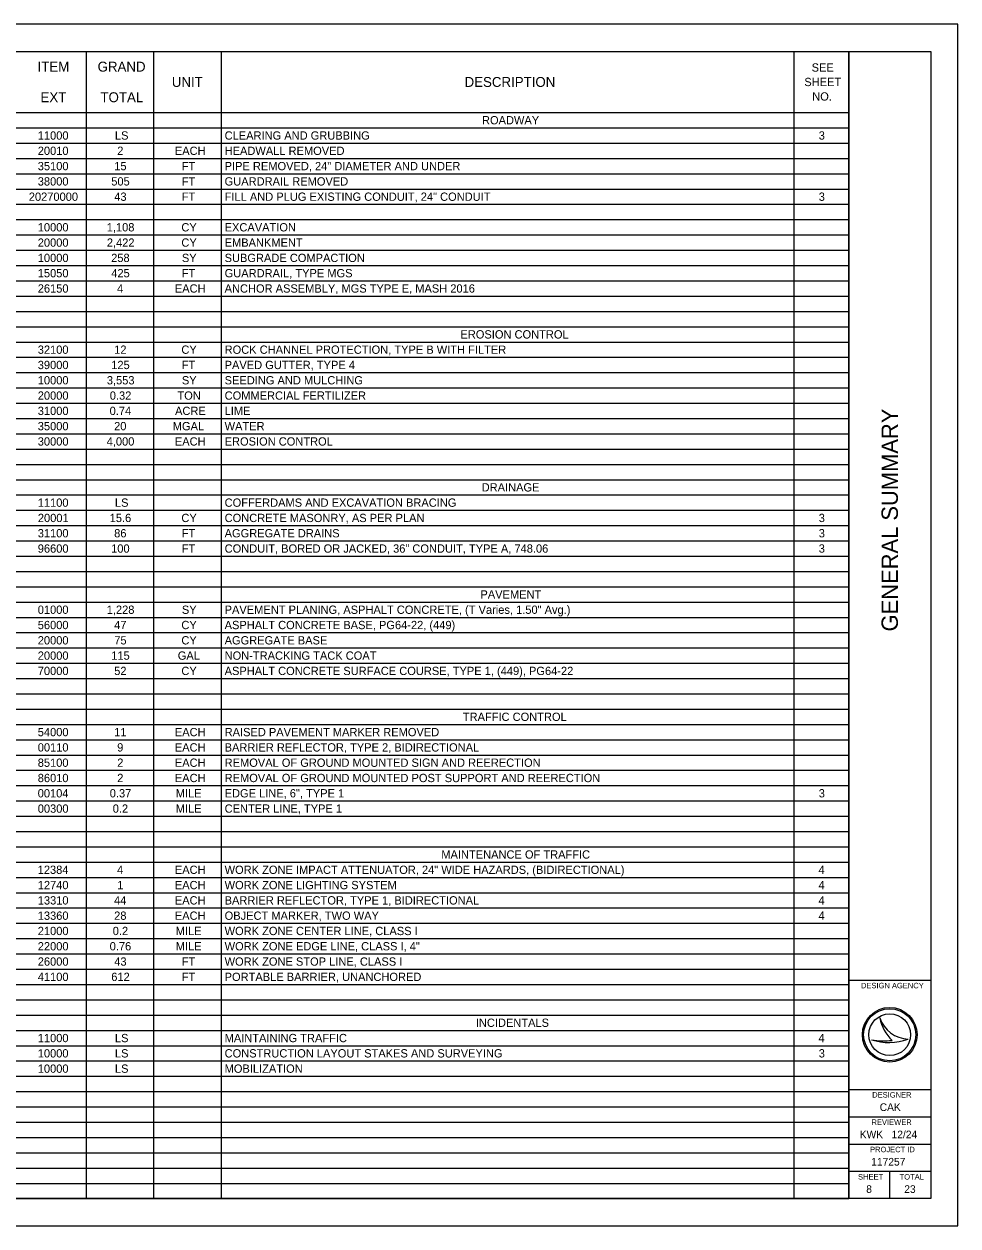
# Model space of a CAD drawing. Extents: x 0 to 34, y 0 to 22.
# Drawn here: x 16.9 to 34, y 0 to 22 of the extents above; entities that cross this region are included whole.
import ezdxf

# ---------------------------------------------------------------- set-up
doc = ezdxf.new("R2010")
doc.units = 0
for name, color, linetype in [('SH_Border', 7, 'Continuous'), ('SH_Cut_Line', 7, 'Continuous'), ('SH_Data', 7, 'Continuous'), ('SH_Text', 7, 'Continuous')]:
    doc.layers.add(name, color=color, linetype=linetype)

msp = doc.modelspace()

# ---------------------------------------------------------------- linework, layer by layer
at = {"layer": 'SH_Border'}
for p, q in [((32, 0.5), (32, 21.5)), ((32, 4.5), (33.5, 4.5)), ((32, 2.5), (33.5, 2.5)), ((32, 2), (33.5, 2)), ((32, 1.5), (33.5, 1.5)), ((32, 1), (33.5, 1))]:
    msp.add_line(p, q, dxfattribs=at)
msp.add_lwpolyline([(1.5, 21.5), (33.5, 21.5), (33.5, 0.5), (1.5, 0.5)], close=True, dxfattribs=at)
at = {"layer": 'SH_Cut_Line'}
msp.add_lwpolyline([(0, 0), (34, 0), (34, 22), (0, 22)], close=True, dxfattribs=at)
at = {"layer": 'SH_Data'}
for p, q in [((32.567, 3.81), (32.567, 3.81)), ((32.417, 3.41), (32.417, 3.41)), ((32.75, 3.5), (32.75, 3.5)), ((33.087, 3.419), (33.087, 3.419)), ((32.75, 0.5), (32.75, 1)), ((32.375, 0.675), (32.375, 0.675))]:
    msp.add_line(p, q, dxfattribs=at)
for radius in [0.5, 0.477, 0.477, 0.382]:
    msp.add_circle((32.75, 3.5), radius, dxfattribs=at)
for centre, radius, start, end in [((33.116, 3.998), 0.58, 198.9257, 198.9319), ((33.347, 3.97), 0.796, 191.6379, 191.6421), ((33.116, 3.998), 0.58, 198.9319, 267.1657), ((33.347, 3.97), 0.796, 191.6421, 226.0947), ((32.739, 4.37), 1.013, 251.4576, 290.0832), ((32.648, 4.654), 1.266, 259.4964, 259.4995), ((32.739, 4.37), 1.013, 251.4527, 251.4576), ((32.648, 4.654), 1.266, 259.4995, 276.6672)]:
    msp.add_arc(centre, radius, start, end, dxfattribs=at)
at = {"layer": 'SH_Text'}
for p, q in [((1.5, 21.5), (32, 21.5)), ((18.035, 21.5), (18.035, 0.5)), ((19.27, 21.5), (19.27, 0.5)), ((20.505, 21.5), (20.505, 0.5)), ((30.995, 21.5), (30.995, 0.5)), ((32, 21.5), (32, 0.5)), ((1.5, 20.38), (32, 20.38)), ((1.5, 20.1), (32, 20.1)), ((1.5, 19.82), (32, 19.82)), ((1.5, 19.54), (32, 19.54)), ((1.5, 19.26), (32, 19.26)), ((1.5, 18.98), (32, 18.98)), ((1.5, 18.7), (32, 18.7)), ((1.5, 18.42), (32, 18.42)), ((1.5, 18.14), (32, 18.14)), ((1.5, 17.86), (32, 17.86)), ((1.5, 17.58), (32, 17.58)), ((1.5, 17.3), (32, 17.3)), ((1.5, 17.02), (32, 17.02)), ((1.5, 16.74), (32, 16.74)), ((1.5, 16.46), (32, 16.46)), ((1.5, 16.18), (32, 16.18)), ((1.5, 15.9), (32, 15.9)), ((1.5, 15.62), (32, 15.62)), ((1.5, 15.34), (32, 15.34)), ((1.5, 15.06), (32, 15.06)), ((1.5, 14.78), (32, 14.78)), ((1.5, 14.5), (32, 14.5)), ((1.5, 14.22), (32, 14.22)), ((1.5, 13.94), (32, 13.94)), ((1.5, 13.66), (32, 13.66)), ((1.5, 13.38), (32, 13.38)), ((1.5, 13.1), (32, 13.1)), ((1.5, 12.82), (32, 12.82)), ((1.5, 12.54), (32, 12.54)), ((1.5, 12.26), (32, 12.26)), ((1.5, 11.98), (32, 11.98)), ((1.5, 11.7), (32, 11.7)), ((1.5, 11.42), (32, 11.42)), ((1.5, 11.14), (32, 11.14)), ((1.5, 10.86), (32, 10.86)), ((1.5, 10.58), (32, 10.58)), ((1.5, 10.3), (32, 10.3)), ((1.5, 10.02), (32, 10.02)), ((1.5, 9.74), (32, 9.74)), ((1.5, 9.46), (32, 9.46)), ((1.5, 9.18), (32, 9.18)), ((1.5, 8.9), (32, 8.9)), ((1.5, 8.62), (32, 8.62)), ((1.5, 8.34), (32, 8.34)), ((1.5, 8.06), (32, 8.06)), ((1.5, 7.78), (32, 7.78)), ((1.5, 7.5), (32, 7.5)), ((1.5, 7.22), (32, 7.22)), ((1.5, 6.94), (32, 6.94)), ((1.5, 6.66), (32, 6.66)), ((1.5, 6.38), (32, 6.38)), ((1.5, 6.1), (32, 6.1)), ((1.5, 5.82), (32, 5.82)), ((1.5, 5.54), (32, 5.54)), ((1.5, 5.26), (32, 5.26)), ((1.5, 4.98), (32, 4.98)), ((1.5, 4.7), (32, 4.7)), ((1.5, 4.42), (32, 4.42)), ((1.5, 4.14), (32, 4.14)), ((1.5, 3.86), (32, 3.86)), ((1.5, 3.58), (32, 3.58)), ((1.5, 3.3), (32, 3.3)), ((1.5, 3.02), (32, 3.02)), ((1.5, 2.74), (32, 2.74)), ((1.5, 2.46), (32, 2.46)), ((1.5, 2.18), (32, 2.18)), ((1.5, 1.9), (32, 1.9)), ((1.5, 1.62), (32, 1.62)), ((1.5, 1.34), (32, 1.34)), ((1.5, 1.06), (32, 1.06)), ((1.5, 0.78), (32, 0.78)), ((1.5, 0.5), (32, 0.5))]:
    msp.add_line(p, q, dxfattribs=at)

# ---------------------------------------------------------------- texts
at = {"layer": 'SH_Data'}
msp.add_text('GENERAL SUMMARY', height=0.3, rotation=90, dxfattribs=at).set_placement((32.9, 10.882))
for s, height, p in [('DESIGN AGENCY', 0.1, (32.223, 4.35)), ('DESIGNER', 0.1, (32.429, 2.35)), ('CAK', 0.14, (32.567, 2.105)), ('REVIEWER', 0.1, (32.416, 1.85)), ('KWK   12/24', 0.14, (32.202, 1.605)), ('PROJECT ID', 0.1, (32.39, 1.35)), ('117257', 0.14, (32.412, 1.105)), ('SHEET', 0.1, (32.17, 0.85)), ('TOTAL', 0.1, (32.931, 0.85)), ('8', 0.14, (32.32, 0.605)), ('23', 0.14, (33.017, 0.605))]:
    msp.add_text(s, height=height, dxfattribs=at).set_placement(p)
at = {"layer": 'SH_Text'}
for s, height, p in [('ITEM', 0.1818, (17.145, 21.129)), ('GRAND', 0.1818, (18.245, 21.129)), ('SEE ', 0.1515, (31.32, 21.129)), ('UNIT', 0.1818, (19.604, 20.849)), ('DESCRIPTION', 0.18184, (24.965, 20.849)), ('SHEET ', 0.1515, (31.187, 20.864)), ('EXT', 0.1818, (17.199, 20.569)), ('TOTAL', 0.1818, (18.297, 20.569)), ('NO.', 0.1515, (31.331, 20.599)), ('ROADWAY', 0.1515, (25.284, 20.164)), ('11000', 0.1515, (17.149, 19.884)), ('LS', 0.1515, (18.562, 19.884)), ('CLEARING AND GRUBBING', 0.15153, (20.571, 19.884)), ('3', 0.152, (31.45, 19.884)), ('20010', 0.1515, (17.149, 19.604)), ('2', 0.152, (18.604, 19.604)), ('EACH', 0.1515, (19.659, 19.604)), ('HEADWALL REMOVED', 0.15153, (20.571, 19.604)), ('35100', 0.1515, (17.149, 19.324)), ('15', 0.1515, (18.55, 19.324)), ('FT', 0.1515, (19.786, 19.324)), ('PIPE REMOVED, 24" DIAMETER AND UNDER', 0.15153, (20.571, 19.324)), ('38000', 0.1515, (17.149, 19.044)), ('505', 0.1515, (18.495, 19.044)), ('FT', 0.1515, (19.786, 19.044)), ('GUARDRAIL REMOVED', 0.15153, (20.571, 19.044)), ('20270000', 0.1515, (16.985, 18.764)), ('43', 0.1515, (18.55, 18.764)), ('FT', 0.1515, (19.786, 18.764)), ('FILL AND PLUG EXISTING CONDUIT, 24" CONDUIT', 0.15153, (20.571, 18.764)), ('3', 0.152, (31.45, 18.764)), ('10000', 0.1515, (17.149, 18.204)), ('1,108', 0.1515, (18.412, 18.204)), ('CY', 0.1515, (19.779, 18.204)), ('EXCAVATION', 0.1515, (20.571, 18.204)), ('20000', 0.1515, (17.149, 17.924)), ('2,422', 0.1515, (18.414, 17.924)), ('CY', 0.1515, (19.779, 17.924)), ('EMBANKMENT', 0.1515, (20.571, 17.924)), ('10000', 0.1515, (17.149, 17.644)), ('258', 0.1515, (18.493, 17.644)), ('SY', 0.1515, (19.788, 17.644)), ('SUBGRADE COMPACTION', 0.15153, (20.571, 17.644)), ('15050', 0.1515, (17.149, 17.364)), ('425', 0.1515, (18.495, 17.364)), ('FT', 0.1515, (19.786, 17.364)), ('GUARDRAIL, TYPE MGS', 0.15153, (20.571, 17.364)), ('26150', 0.1515, (17.149, 17.084)), ('4', 0.152, (18.601, 17.084)), ('EACH', 0.1515, (19.659, 17.084)), ('ANCHOR ASSEMBLY, MGS TYPE E, MASH 2016', 0.15153, (20.571, 17.084)), ('EROSION CONTROL', 0.15153, (24.889, 16.244)), ('32100', 0.1515, (17.149, 15.964)), ('12', 0.1515, (18.549, 15.964)), ('CY', 0.1515, (19.779, 15.964)), ('ROCK CHANNEL PROTECTION, TYPE B WITH FILTER', 0.15153, (20.571, 15.964)), ('39000', 0.1515, (17.149, 15.684)), ('125', 0.1515, (18.495, 15.684)), ('FT', 0.1515, (19.786, 15.684)), ('PAVED GUTTER, TYPE 4', 0.15153, (20.571, 15.684)), ('10000', 0.1515, (17.149, 15.404)), ('3,553', 0.1515, (18.414, 15.404)), ('SY', 0.1515, (19.788, 15.404)), ('SEEDING AND MULCHING', 0.15153, (20.571, 15.404)), ('20000', 0.1515, (17.149, 15.124)), ('0.32', 0.1515, (18.468, 15.124)), ('TON', 0.1515, (19.707, 15.124)), ('COMMERCIAL FERTILIZER', 0.15153, (20.571, 15.124)), ('31000', 0.1515, (17.149, 14.844)), ('0.74', 0.1515, (18.465, 14.844)), ('ACRE', 0.1515, (19.663, 14.844)), ('LIME', 0.1515, (20.571, 14.844)), ('35000', 0.1515, (17.149, 14.564)), ('20', 0.1515, (18.547, 14.564)), ('MGAL', 0.1515, (19.621, 14.564)), ('WATER', 0.1515, (20.571, 14.564)), ('30000', 0.1515, (17.149, 14.284)), ('4,000', 0.1515, (18.411, 14.284)), ('EACH', 0.1515, (19.659, 14.284)), ('EROSION CONTROL', 0.15153, (20.571, 14.284)), ('DRAINAGE', 0.1515, (25.278, 13.444)), ('11100', 0.1515, (17.149, 13.164)), ('LS', 0.1515, (18.562, 13.164)), ('COFFERDAMS AND EXCAVATION BRACING', 0.15153, (20.571, 13.164)), ('20001', 0.1515, (17.151, 12.884)), ('15.6', 0.1515, (18.466, 12.884)), ('CY', 0.1515, (19.779, 12.884)), ('CONCRETE MASONRY, AS PER PLAN', 0.15153, (20.571, 12.884)), ('3', 0.152, (31.45, 12.884)), ('31100', 0.1515, (17.149, 12.604)), ('86', 0.1515, (18.548, 12.604)), ('FT', 0.1515, (19.786, 12.604)), ('AGGREGATE DRAINS', 0.15153, (20.571, 12.604)), ('3', 0.152, (31.45, 12.604)), ('96600', 0.1515, (17.149, 12.324)), ('100', 0.1515, (18.493, 12.324)), ('FT', 0.1515, (19.786, 12.324)), ('CONDUIT, BORED OR JACKED, 36" CONDUIT, TYPE A, 748.06', 0.15153, (20.571, 12.324)), ('3', 0.152, (31.45, 12.324)), ('PAVEMENT', 0.1515, (25.255, 11.484)), ('01000', 0.1515, (17.149, 11.204)), ('1,228', 0.1515, (18.412, 11.204)), ('SY', 0.1515, (19.788, 11.204)), ('PAVEMENT PLANING, ASPHALT CONCRETE, (T Varies, 1.50" Avg.)', 0.15153, (20.571, 11.204)), ('56000', 0.1515, (17.149, 10.924)), ('47', 0.1515, (18.548, 10.924)), ('CY', 0.1515, (19.779, 10.924)), ('ASPHALT CONCRETE BASE, PG64-22, (449)', 0.15153, (20.571, 10.924)), ('20000', 0.1515, (17.149, 10.644)), ('75', 0.1515, (18.55, 10.644)), ('CY', 0.1515, (19.779, 10.644)), ('AGGREGATE BASE', 0.15153, (20.571, 10.644)), ('20000', 0.1515, (17.149, 10.364)), ('115', 0.1515, (18.495, 10.364)), ('GAL', 0.1515, (19.713, 10.364)), ('NON-TRACKING TACK COAT', 0.15153, (20.571, 10.364)), ('70000', 0.1515, (17.149, 10.084)), ('52', 0.1515, (18.549, 10.084)), ('CY', 0.1515, (19.779, 10.084)), ('ASPHALT CONCRETE SURFACE COURSE, TYPE 1, (449), PG64-22', 0.15153, (20.571, 10.084)), ('TRAFFIC CONTROL', 0.15153, (24.933, 9.244)), ('54000', 0.1515, (17.149, 8.964)), ('11', 0.1515, (18.549, 8.964)), ('EACH', 0.1515, (19.659, 8.964)), ('RAISED PAVEMENT MARKER REMOVED', 0.15153, (20.571, 8.964)), ('00110', 0.1515, (17.149, 8.684)), ('9', 0.152, (18.603, 8.684)), ('EACH', 0.1515, (19.659, 8.684)), ('BARRIER REFLECTOR, TYPE 2, BIDIRECTIONAL', 0.15153, (20.571, 8.684)), ('85100', 0.1515, (17.149, 8.404)), ('2', 0.152, (18.604, 8.404)), ('EACH', 0.1515, (19.659, 8.404)), ('REMOVAL OF GROUND MOUNTED SIGN AND REERECTION', 0.15153, (20.571, 8.404)), ('86010', 0.1515, (17.149, 8.124)), ('2', 0.152, (18.604, 8.124)), ('EACH', 0.1515, (19.659, 8.124)), ('REMOVAL OF GROUND MOUNTED POST SUPPORT AND REERECTION', 0.15153, (20.571, 8.124)), ('00104', 0.1515, (17.148, 7.844)), ('0.37', 0.1515, (18.467, 7.844)), ('MILE', 0.1515, (19.676, 7.844)), ('EDGE LINE, 6", TYPE 1', 0.15153, (20.571, 7.844)), ('3', 0.152, (31.45, 7.844)), ('00300', 0.1515, (17.149, 7.564)), ('0.2', 0.1515, (18.522, 7.564)), ('MILE', 0.1515, (19.676, 7.564)), ('CENTER LINE, TYPE 1', 0.15153, (20.571, 7.564)), ('MAINTENANCE OF TRAFFIC', 0.15153, (24.539, 6.724)), ('WORK ZONE IMPACT ATTENUATOR, 24" WIDE HAZARDS, (BIDIRECTIONAL)', 0.15153, (20.571, 6.444)), ('12384', 0.1515, (17.148, 6.444)), ('4', 0.152, (18.601, 6.444)), ('EACH', 0.1515, (19.659, 6.444)), ('4', 0.152, (31.446, 6.444)), ('12740', 0.1515, (17.149, 6.164)), ('1', 0.152, (18.604, 6.164)), ('EACH', 0.1515, (19.659, 6.164)), ('WORK ZONE LIGHTING SYSTEM', 0.15153, (20.571, 6.164)), ('4', 0.152, (31.446, 6.164)), ('13310', 0.1515, (17.149, 5.884)), ('44', 0.1515, (18.546, 5.884)), ('EACH', 0.1515, (19.659, 5.884)), ('BARRIER REFLECTOR, TYPE 1, BIDIRECTIONAL', 0.15153, (20.571, 5.884)), ('4', 0.152, (31.446, 5.884)), ('13360', 0.1515, (17.149, 5.604)), ('28', 0.1515, (18.548, 5.604)), ('EACH', 0.1515, (19.659, 5.604)), ('OBJECT MARKER, TWO WAY', 0.15153, (20.571, 5.604)), ('4', 0.152, (31.446, 5.604)), ('21000', 0.1515, (17.149, 5.324)), ('0.2', 0.1515, (18.522, 5.324)), ('MILE', 0.1515, (19.676, 5.324)), ('WORK ZONE CENTER LINE, CLASS I', 0.15153, (20.571, 5.324)), ('22000', 0.1515, (17.149, 5.044)), ('0.76', 0.1515, (18.466, 5.044)), ('MILE', 0.1515, (19.676, 5.044)), ('WORK ZONE EDGE LINE, CLASS I, 4"', 0.15153, (20.571, 5.044)), ('26000', 0.1515, (17.149, 4.764)), ('43', 0.1515, (18.55, 4.764)), ('FT', 0.1515, (19.786, 4.764)), ('WORK ZONE STOP LINE, CLASS I', 0.15153, (20.571, 4.764)), ('41100', 0.1515, (17.149, 4.484)), ('612', 0.1515, (18.495, 4.484)), ('FT', 0.1515, (19.786, 4.484)), ('PORTABLE BARRIER, UNANCHORED', 0.15153, (20.571, 4.484)), ('INCIDENTALS', 0.15153, (25.171, 3.644)), ('11000', 0.1515, (17.149, 3.364)), ('LS', 0.1515, (18.562, 3.364)), ('MAINTAINING TRAFFIC', 0.15153, (20.571, 3.364)), ('4', 0.152, (31.446, 3.364)), ('10000', 0.1515, (17.149, 3.084)), ('LS', 0.1515, (18.562, 3.084)), ('CONSTRUCTION LAYOUT STAKES AND SURVEYING', 0.15153, (20.571, 3.084)), ('3', 0.152, (31.45, 3.084)), ('10000', 0.1515, (17.149, 2.804)), ('LS', 0.1515, (18.562, 2.804)), ('MOBILIZATION', 0.15153, (20.571, 2.804))]:
    msp.add_text(s, height=height, dxfattribs=at).set_placement(p)

doc.saveas('drawing.dxf')
